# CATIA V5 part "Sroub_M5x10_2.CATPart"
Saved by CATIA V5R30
Part number: Sroub_M5x10_2
Definition: E 1220_5x10_1
Nomenclature: E 1220_5x10_1
Source: Unknown
Description: PART--DESC
Bounding box of the stored display mesh (mm): x -209 to -199, y 85.01 to 94.99, z -223.5 to -213.5
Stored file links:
  E:\Bakalarka\Model\Forma_v7\Sroub_M5x10_2.CATPart
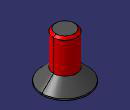
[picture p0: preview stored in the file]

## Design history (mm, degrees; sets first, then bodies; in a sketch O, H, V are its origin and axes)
Body1 "MANIFOLD_SOLID_BREP #4042" (main body)
  Solid1: solid without history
